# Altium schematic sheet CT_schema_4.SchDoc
size 276 x 169 mm
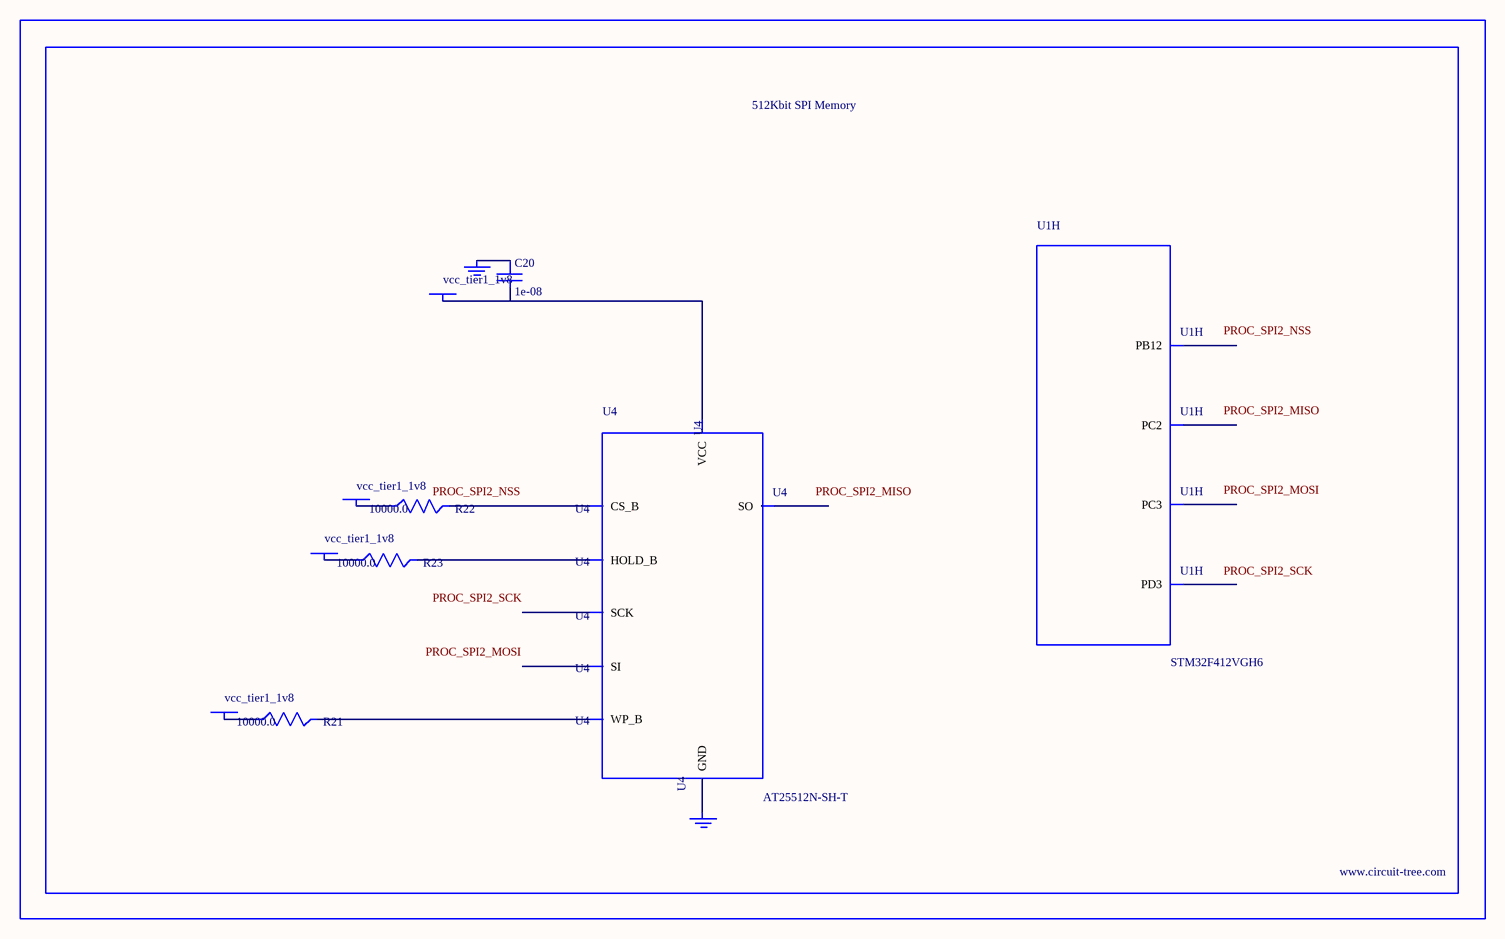
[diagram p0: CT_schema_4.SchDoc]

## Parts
BORDER3  (no value)
C20  1e-08  [C0402]
GND_INSTANCE_3_0  (no value)
GND_INSTANCE_3_1  (no value)
POWER_INSTANCE_3_0  vcc_tier1_1v8
POWER_INSTANCE_3_1  vcc_tier1_1v8
POWER_INSTANCE_3_2  vcc_tier1_1v8
POWER_INSTANCE_3_3  vcc_tier1_1v8
R21  10000.0  [R0603]
R22  10000.0  [R0603]
R23  10000.0  [R0603]
U1  STM32F412VGH6  [UFBGA100]  (part H of 11)
U4  AT25512N-SH-T  [SOIC-8]

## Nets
NetC20_1: C20.1 GND_INSTANCE_3_0.0(GND)
NetC20_2: C20.2 POWER_INSTANCE_3_3.0(PWR) U4.8(VCC)
NetGND_INSTANCE_3_1_0: GND_INSTANCE_3_1.0(GND) U4.4(GND)
NetPOWER_INSTANCE_3_0_0: POWER_INSTANCE_3_0.0(PWR) R22.1
NetPOWER_INSTANCE_3_1_0: POWER_INSTANCE_3_1.0(PWR) R21.1
NetPOWER_INSTANCE_3_2_0: POWER_INSTANCE_3_2.0(PWR) R23.1
NetR21_2: R21.2 U4.3(WP_B)
NetR22_2: R22.2 U4.1(CS_B)
NetR23_2: R23.2 U4.7(HOLD_B)

Not connected (* = marked no-connect by the designer): U1 B8(PD3) J3(PC2) K2(PC3) L12(PB12); U4 2(SO) 5(SI) 6(SCK)

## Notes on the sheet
- Labels drawn without touching a wire or pin: PROC_SPI2_MISO, PROC_SPI2_MOSI, PROC_SPI2_NSS, PROC_SPI2_SCK

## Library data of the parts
BORDER3 = BORDER_PAGE3
C20 = C0402C103K3RAC
GND_INSTANCE_3_0 GND_INSTANCE_3_1 = GND
POWER_INSTANCE_3_0-POWER_INSTANCE_3_3 = PWR
R21-R23 = RC0603JR-0710KL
